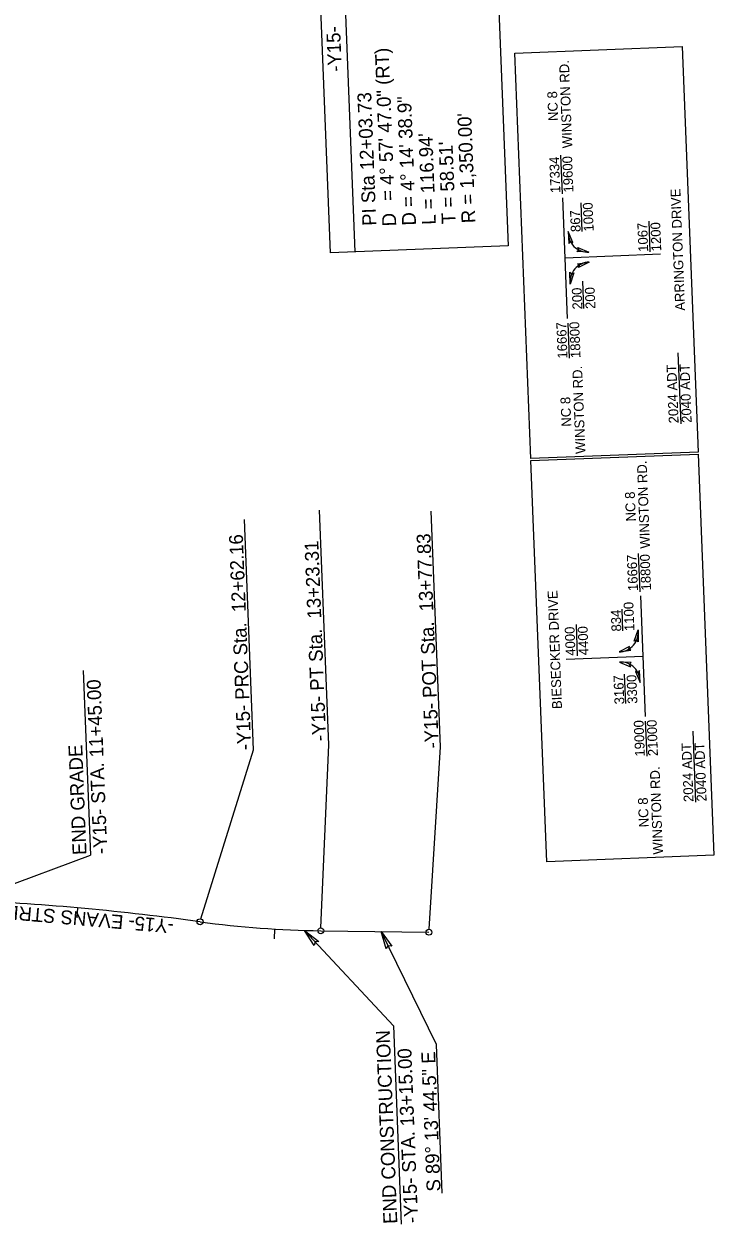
# Model space of a CAD drawing. Extents: x 1627861 to 1629601, y 761281 to 766239.
# Drawn here: x 1628544 to 1628892, y 764835 to 765440 of the extents above; entities that cross this region are included whole.
import ezdxf

# ---------------------------------------------------------------- set-up
doc = ezdxf.new("R2010")
doc.units = 0
for name, color, linetype in [('Cogo Default Point CELL', 7, 'Continuous'), ('Default', 7, 'Continuous'), ('Exist Other Culture Sign Leader', 7, 'Continuous'), ('Exist Property Tie Line Text', 7, 'Continuous'), ('Exist Right of Way Line Leader', 7, 'Continuous'), ('Exist Utilities Gas Meter CELL', 7, 'Continuous'), ('Exist Utilities Gas Meter Cogo Number', 7, 'Continuous'), ('Exist Utilities Gas UG Line Text', 7, 'Continuous'), ('Exist Utilities Water UG Line SUE LOS B Cogo Point CELL', 7, 'Continuous'), ('Scratch_Level_0', 7, 'Continuous')]:
    doc.layers.add(name, color=color, linetype=linetype)

msp = doc.modelspace()

# ---------------------------------------------------------------- linework, layer by layer
at = {"layer": 'Default'}
for p, q in [((1628815.59, 765354.49), (1628814.82, 765373.84)), ((1628818.09, 765291.61), (1628815.69, 765352.48)), ((1628825.51, 765335.42), (1628824.94, 765349.86)), ((1628859.87, 765325.16), (1628859.26, 765340.67)), ((1628864.95, 765323.94), (1628816.89, 765322.04)), ((1628826.36, 765296.58), (1628825.81, 765310.39)), ((1628819.18, 765271.53), (1628818.49, 765289.18)), ((1628875.38, 765238.49), (1628873.96, 765274.31)), ((1628854.75, 765153.76), (1628853.99, 765173.1)), ((1628857.52, 765090.88), (1628855.12, 765151.75)), ((1628846.05, 765133.95), (1628845.62, 765144.99)), ((1628823.21, 765121.43), (1628822.59, 765137.21)), ((1628817.51, 765119.79), (1628856.32, 765121.32)), ((1628847.53, 765097.42), (1628846.95, 765112.1)), ((1628858.23, 765070.78), (1628857.53, 765088.43)), ((1628882.91, 765047.52), (1628881.49, 765083.34))]:
    msp.add_line(p, q, dxfattribs=at)
for points in [[(1628799.63, 765220.85), (1628791.56, 765425.41), (1628875.93, 765428.73), (1628883.99, 765224.18)], [(1628807.65, 765017.52), (1628799.67, 765219.86), (1628884.03, 765223.18), (1628892.01, 765020.85)]]:
    msp.add_lwpolyline(points, close=True, dxfattribs=at)
for centre, start, end in [((1628828.34, 765334.95), 177.12188, 273.30228), ((1628829.32, 765310.08), 91.2141, 187.3945), ((1628843.89, 765133.28), 271.2141, 7.3945), ((1628844.87, 765108.41), 357.12188, 93.30228)]:
    msp.add_arc(centre, 9.89, start, end, dxfattribs=at)
at = {"layer": 'Exist Other Culture Sign Leader'}
for p, q in [((1628685.39, 764982.91), (1628730.27, 764934.71)), ((1628730.27, 764934.71), (1628734.21, 764834.84))]:
    msp.add_line(p, q, dxfattribs=at)
at = {"layer": 'Exist Property Tie Line Text'}
for p, q in [((1628570.99, 764994.27), (1628570.54, 764989.29)), ((1628670.4, 764983.58), (1628670.1, 764978.59))]:
    msp.add_line(p, q, dxfattribs=at)
at = {"layer": 'Exist Right of Way Line Leader'}
for p, q in [((1628659.77, 765074), (1628655.18, 765190.25)), ((1628697.77, 765076.5), (1628693.1, 765194.91)), ((1628754, 765075.59), (1628749.31, 765194.41)), ((1628693.76, 764984.22), (1628697.77, 765076.5)), ((1628748.28, 764983.49), (1628754, 765075.59)), ((1628633.2, 764988.71), (1628659.77, 765074)), ((1628751.97, 764925.3), (1628724.09, 764982.32)), ((1628754.92, 764850.36), (1628751.97, 764925.3))]:
    msp.add_line(p, q, dxfattribs=at)
for centre in [(1628632.76, 764987.28), (1628693.69, 764982.73), (1628748.2, 764981.99)]:
    msp.add_circle(centre, 1.5, dxfattribs=at)
at = {"layer": 'Exist Utilities Gas Meter CELL'}
msp.add_line((1628693.69, 764982.73), (1628748.2, 764981.99), dxfattribs=at)
for centre, radius, start, end in [((1628450.06, 763649.7), 1350, 82.22219, 87.18524), ((1628700.42, 765482.68), 500, 262.22219, 269.22904)]:
    msp.add_arc(centre, radius, start, end, dxfattribs=at)
at = {"layer": 'Exist Utilities Gas Meter Cogo Number'}
for points in [[(1628690.39, 764975.26), (1628685.39, 764982.91), (1628692.72, 764977.37), (1628690.77, 764977.13)], [(1628726.65, 764973.55), (1628724.09, 764982.32), (1628729.5, 764974.89), (1628727.56, 764975.22)]]:
    msp.add_lwpolyline(points, close=True, dxfattribs=at)
at = {"layer": 'Exist Utilities Gas UG Line Text'}
msp.add_line((1628702.21, 765546.28), (1628710.92, 765325.21), dxfattribs=at)
msp.add_lwpolyline([(1628698.59, 765324.72), (1628689.87, 765545.8), (1628779.41, 765549.33), (1628788.13, 765328.25)], close=True, dxfattribs=at)
at = {"layer": 'Exist Utilities Water UG Line SUE LOS B Cogo Point CELL'}
for points in [[(1628820.83, 765329.91), (1628818.46, 765335.45), (1628818.82, 765329.4), (1628819.67, 765330.38)], [(1628823.36, 765327.41), (1628828.91, 765325.07), (1628822.86, 765325.4), (1628823.84, 765326.25)], [(1628823.14, 765319.19), (1628829.11, 765319.97), (1628823.73, 765317.19), (1628824.14, 765318.43)], [(1628821.37, 765314.54), (1628819.51, 765308.81), (1628819.32, 765314.86), (1628820.25, 765313.96)], [(1628851.78, 765128.85), (1628853.7, 765134.55), (1628853.82, 765128.5), (1628852.9, 765129.41)], [(1628849.45, 765126.16), (1628844.1, 765123.39), (1628850.11, 765124.19), (1628849.06, 765124.97)], [(1628850.31, 765117.97), (1628844.3, 765118.29), (1628849.89, 765115.94), (1628849.38, 765117.14)], [(1628852.45, 765113.48), (1628854.75, 765107.92), (1628854.47, 765113.97), (1628853.61, 765113)]]:
    msp.add_lwpolyline(points, close=True, dxfattribs=at)
at = {"layer": 'Scratch_Level_0'}
for p in [(1628573.77, 765113.96), (1628516.13, 764998.08)]:
    msp.add_line(p, (1628577.44, 765020.93), dxfattribs=at)

# ---------------------------------------------------------------- texts
at = {"layer": 'Cogo Default Point CELL'}
msp.add_text('S 89%%d 13\' 44.5" E', height=7, rotation=92.25819, dxfattribs=at).set_placement((1628754.11, 764851.35))
at = {"layer": 'Default'}
for s, height, p in [('WINSTON RD.', 4.9438, (1628820.55, 765377.53)), ('NC 8', 4.944, (1628813.41, 765391.23)), ('17334', 4.944, (1628814.53, 765354.92)), ('19600', 4.944, (1628821.12, 765355.18)), ('ARRINGTON DRIVE', 4.9438, (1628877.45, 765295.54)), ('1000', 4.944, (1628831.34, 765335.5)), ('867', 4.944, (1628824.76, 765335.24)), ('1067', 4.944, (1628858.85, 765325.26)), ('1200', 4.944, (1628865.44, 765325.52)), ('200', 4.944, (1628825.64, 765296.19)), ('200', 4.944, (1628832.22, 765296.45)), ('16667', 4.944, (1628818.12, 765271.42)), ('18800', 4.944, (1628824.71, 765271.68)), ('2040 ADT', 4.944, (1628880.76, 765239.01)), ('WINSTON RD.', 4.9438, (1628827.2, 765223.36)), ('2024 ADT', 4.944, (1628874.18, 765238.75)), ('NC 8', 4.944, (1628820.06, 765237.06)), ('WINSTON RD.', 4.9438, (1628859.76, 765175.58)), ('NC 8', 4.944, (1628852.62, 765189.28)), ('16667', 4.944, (1628853.7, 765154.18)), ('18800', 4.944, (1628860.28, 765154.44)), ('BIESECKER DRIVE', 4.9438, (1628815.37, 765094.66)), ('1100', 4.944, (1628851.88, 765134.02)), ('834', 4.944, (1628845.3, 765133.76)), ('4000', 4.944, (1628822.19, 765121.53)), ('4400', 4.944, (1628828.78, 765121.79)), ('3167', 4.944, (1628846.81, 765097.03)), ('3300', 4.944, (1628853.4, 765097.29)), ('19000', 4.944, (1628857.16, 765070.68)), ('21000', 4.944, (1628863.75, 765070.94)), ('2024 ADT', 4.944, (1628881.71, 765047.78)), ('2040 ADT', 4.944, (1628888.3, 765048.04)), ('WINSTON RD.', 4.9438, (1628866.29, 765021.3)), ('NC 8', 4.944, (1628859.15, 765035))]:
    msp.add_text(s, height=height, rotation=92.25819, dxfattribs=at).set_placement(p)
at = {"layer": 'Exist Other Culture Sign Leader'}
for s, rotation, p in [('-Y15- STA. 11+45.00', 92.25819, (1628586.02, 765021.53)), ('END GRADE', 92.25819, (1628575.53, 765021.12)), ('-Y15- EVANS STREET', 175.04694, (1628619.76, 764988.3)), ('END CONSTRUCTION', 92.25819, (1628732.3, 764835.04)), ('-Y15- STA. 13+15.00', 92.25819, (1628742.79, 764835.45))]:
    msp.add_text(s, height=7, rotation=rotation, dxfattribs=at).set_placement(p)
at = {"layer": 'Exist Right of Way Line Leader'}
for s, p in [('-Y15- PRC Sta.  12+62.16', (1628658.63, 765073.93)), ('-Y15- PT Sta.  13+23.31', (1628696.39, 765078.48)), ('-Y15- POT Sta.  13+77.83', (1628753.21, 765074.86))]:
    msp.add_text(s, height=7, rotation=92.25819, dxfattribs=at).set_placement(p)
at = {"layer": 'Exist Utilities Gas UG Line Text'}
for s, p in [('-Y15-', (1628704.29, 765416.15)), ('= 4%%d 57\' 47.0" (RT)', (1628730.95, 765350.99)), ('PI Sta 12+03.73', (1628721.73, 765338.44)), ('D = 4%%d 14\' 38.9"', (1628741.74, 765338.56)), ("R = 1,350.00'", (1628771.72, 765339.74)), ("L = 116.94'", (1628751.73, 765338.95)), ("T = 58.51'", (1628761.73, 765339.34)), ('D', (1628731.75, 765338.16))]:
    msp.add_text(s, height=7, rotation=92.25819, dxfattribs=at).set_placement(p)

doc.saveas('drawing.dxf')
